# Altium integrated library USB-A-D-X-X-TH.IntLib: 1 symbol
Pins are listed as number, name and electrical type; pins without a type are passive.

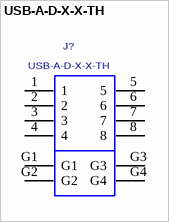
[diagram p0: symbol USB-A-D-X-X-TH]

## USB-A-D-X-X-TH
designator J?
USB A, DOUBLE, THROUGH HOLE.; MANUFACTURER: SAMTEC
footprint USB-A-D-X-X-TH
pins: 1, 2, 3, 4, 5, 6, 7, 8, G1, G2, G3, G4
